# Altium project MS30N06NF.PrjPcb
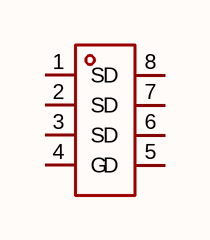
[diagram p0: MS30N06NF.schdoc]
1 sheet, 1 parts. Net scope: global (net labels, ports and power ports of the same name join across sheets).

## Sheet MS30N06NF.schdoc
size 127 x 101 mm

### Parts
Q?  ms30n06nf  [DFN-8_L5.9-W5.1-P1.27-LS6.1-BL-1]  (value not drawn)

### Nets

Not connected (* = marked no-connect by the designer): Q? 1(S) 2(S) 3(S) 4(G) 5(D) 6(D) 7(D) 8(D)

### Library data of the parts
Q? = ms30n06nf: 数量:1个N沟道;漏源电压(Vdss):60V;连续漏极电流(Id):30A;导通电阻(RDS(on)):30mΩ@10V;耗散功率(Pd):35W;阈值电压(Vgs(th)):2.5V;; Manufacturer: MSKSEMI(美森科); AddInBom: yes; ModelId: 4eccc63b9fac4db98821c8b929d34bdb; ModelTransform: 210.03895,242.5192,0,0,0,0,0,0,0; Number: 1个N沟道; Drain to Source Voltage: 60V; Current - Continuous Drain(Id): 30A; Pd - Power Dissipation: 35W; Gate Threshold Voltage (Vgs(th)): 2.5V; Gate Charge(Qg): 16.4nC@10V; Input Capacitance(Ciss): 1.18nF; Reverse Transfer Capacitance (Crss@Vds): 52pF; Output Capacitance(Coss): 80pF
